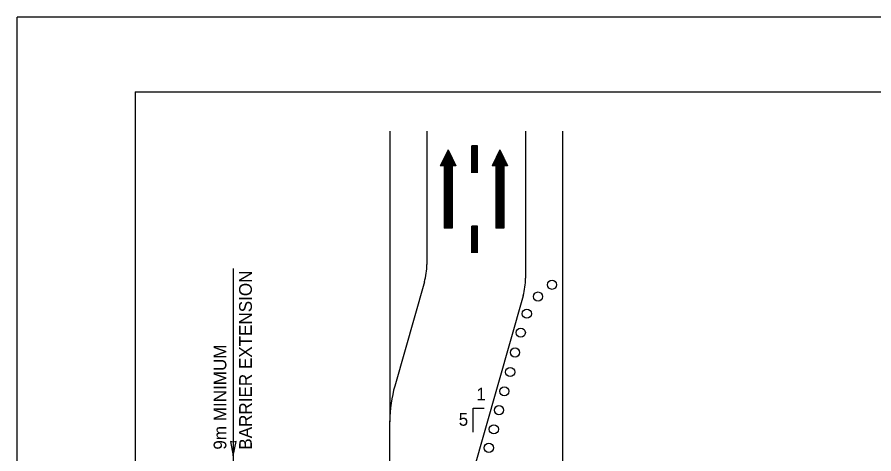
# Model space of a CAD drawing. Extents: x 3033 to 3249, y -403 to -124.
# Drawn here: x 3033.2 to 3167.7, y -192.1 to -123.6 of the extents above; entities that cross this region are included whole.
import ezdxf

# ---------------------------------------------------------------- set-up
doc = ezdxf.new("R2010")
doc.units = 0
for name, color, linetype in [('Level 10', 7, 'Continuous'), ('Level 17', 7, 'Continuous'), ('Level 22', 7, 'Continuous'), ('Level 44', 7, 'Continuous'), ('Level 5', 7, 'Continuous'), ('Level 60', 7, 'Continuous')]:
    doc.layers.add(name, color=color, linetype=linetype)

# ---------------------------------------------------------------- blocks, each defined once
blk = doc.blocks.new('arrow')
at = {"layer": 'Level 60'}
blk.add_lwpolyline([(0.6, 0.12), (0, 0), (0.6, -0.12), (0.56, 0)], close=True, dxfattribs=at)

msp = doc.modelspace()

# ---------------------------------------------------------------- linework, layer by layer
at = {"layer": 'Level 10'}
for p, q in [((3091.73, -141.45), (3091.73, -187.04)), ((3097.53, -141.45), (3097.53, -162.38)), ((3113.02, -141.45), (3113.02, -164.54)), ((3118.82, -141.45), (3118.82, -211.82)), ((3100.87, -144.42), (3099.64, -146.88)), ((3100.56, -145.04), (3100.56, -156.69)), ((3100.72, -144.73), (3100.72, -156.69)), ((3100.87, -144.42), (3100.87, -156.69)), ((3100.87, -144.42), (3102.1, -146.88)), ((3101.02, -144.73), (3101.02, -156.69)), ((3101.18, -145.04), (3101.18, -156.69)), ((3108.98, -144.42), (3107.76, -146.88)), ((3108.68, -145.04), (3108.68, -156.69)), ((3108.83, -144.73), (3108.83, -156.69)), ((3108.98, -144.42), (3108.98, -156.69)), ((3108.98, -144.42), (3110.21, -146.88)), ((3109.14, -144.73), (3109.14, -156.69)), ((3109.29, -145.04), (3109.29, -156.69)), ((3099.8, -146.57), (3099.8, -146.88)), ((3099.95, -146.26), (3099.95, -146.88)), ((3100.1, -145.96), (3100.1, -146.88)), ((3100.26, -145.65), (3100.26, -156.69)), ((3100.41, -145.35), (3100.41, -156.69)), ((3101.33, -145.35), (3101.33, -156.69)), ((3101.48, -145.65), (3101.48, -156.69)), ((3101.64, -145.96), (3101.64, -146.88)), ((3101.79, -146.26), (3101.79, -146.88)), ((3101.94, -146.57), (3101.94, -146.88)), ((3107.91, -146.57), (3107.91, -146.88)), ((3108.06, -146.26), (3108.06, -146.88)), ((3108.22, -145.96), (3108.22, -146.88)), ((3108.37, -145.65), (3108.37, -156.69)), ((3108.52, -145.35), (3108.52, -156.69)), ((3109.44, -145.35), (3109.44, -156.69)), ((3109.6, -145.65), (3109.6, -156.69)), ((3109.75, -145.96), (3109.75, -146.88)), ((3109.9, -146.26), (3109.9, -146.88)), ((3110.06, -146.57), (3110.06, -146.88)), ((3100.26, -146.88), (3099.64, -146.88)), ((3100.26, -146.88), (3100.26, -156.69)), ((3101.48, -146.88), (3101.48, -156.69)), ((3102.1, -146.88), (3101.48, -146.88)), ((3108.37, -146.88), (3107.76, -146.88)), ((3108.37, -146.88), (3108.37, -156.69)), ((3109.6, -146.88), (3109.6, -156.69)), ((3110.21, -146.88), (3109.6, -146.88)), ((3101.48, -156.69), (3100.26, -156.69)), ((3109.6, -156.69), (3108.37, -156.69)), ((3097.15, -165.12), (3092.5, -181.44)), ((3112.63, -167.28), (3101.72, -205.56)), ((3091.73, -284.98), (3091.73, -186.92))]:
    msp.add_line(p, q, dxfattribs=at)
for centre in [(3117.18, -165.56), (3114.98, -167.41), (3113.22, -170.1), (3112.27, -173.06), (3111.37, -176.18), (3110.6, -179.25), (3109.7, -182.26), (3108.85, -185.22), (3108.04, -188.22), (3107.26, -191.13)]:
    msp.add_circle(centre, 0.718, dxfattribs=at)
for centre, radius, start, end in [((3087.53, -162.38), 10, 344.0903, 0), ((3103.02, -164.54), 10, 344.0903, 0), ((3111.73, -186.92), 20, 164.0903, 180)]:
    msp.add_arc(centre, radius, start, end, dxfattribs=at)
at = {"layer": 'Level 17'}
for p in [(3033.21, -402.59), (3249.22, -123.59)]:
    msp.add_line(p, (3033.21, -123.59), dxfattribs=at)
at = {"layer": 'Level 22'}
for q in [(3051.75, -391.78), (3239.21, -135.28)]:
    msp.add_line((3051.75, -135.28), q, dxfattribs=at)
at = {"layer": 'Level 44'}
for p, q in [((3105.48, -143.79), (3104.61, -143.79)), ((3105.48, -156.39), (3104.61, -156.39))]:
    msp.add_line(p, q, dxfattribs=at)
for points in [[(3104.61, -147.98), (3104.61, -143.79)], [(3104.76, -147.98), (3104.76, -143.79)], [(3104.9, -147.98), (3104.9, -143.79)], [(3105.05, -147.98), (3105.05, -143.79)], [(3105.19, -147.98), (3105.19, -143.79)], [(3105.34, -147.98), (3105.34, -143.79)], [(3105.48, -147.98), (3105.48, -143.79)], [(3104.61, -160.57), (3104.61, -156.39)], [(3104.76, -160.57), (3104.76, -156.39)], [(3104.9, -160.57), (3104.9, -156.39)], [(3105.05, -160.57), (3105.05, -156.39)], [(3105.19, -160.57), (3105.19, -156.39)], [(3105.34, -160.57), (3105.34, -156.39)], [(3105.48, -160.57), (3105.48, -156.39)]]:
    msp.add_lwpolyline(points, dxfattribs=at)
at = {"layer": 'Level 5'}
for p, q in [((3067.15, -163.02), (3067.15, -271.59)), ((3104.79, -188.67), (3104.79, -184.91)), ((3104.79, -184.91), (3106.5, -184.91))]:
    msp.add_line(p, q, dxfattribs=at)

# ---------------------------------------------------------------- block references
at = {"layer": 'Level 10', "xscale": 3.75, "yscale": 3.75, "rotation": 90}
msp.add_blockref('arrow', (3067.14, -192.37), dxfattribs=at)

# ---------------------------------------------------------------- texts
at = {"layer": 'Level 44'}
for s, p in [('BARRIER EXTENSION', (3070.06, -191.42)), ('9m MINIMUM', (3066.06, -191.42))]:
    msp.add_text(s, height=2, rotation=90, dxfattribs=at).set_placement(p)
at = {"layer": 'Level 5'}
for s, p in [('1', (3105.3, -183.71)), ('5', (3102.53, -187.67))]:
    msp.add_text(s, height=2, rotation=360, dxfattribs=at).set_placement(p)

doc.saveas('drawing.dxf')
